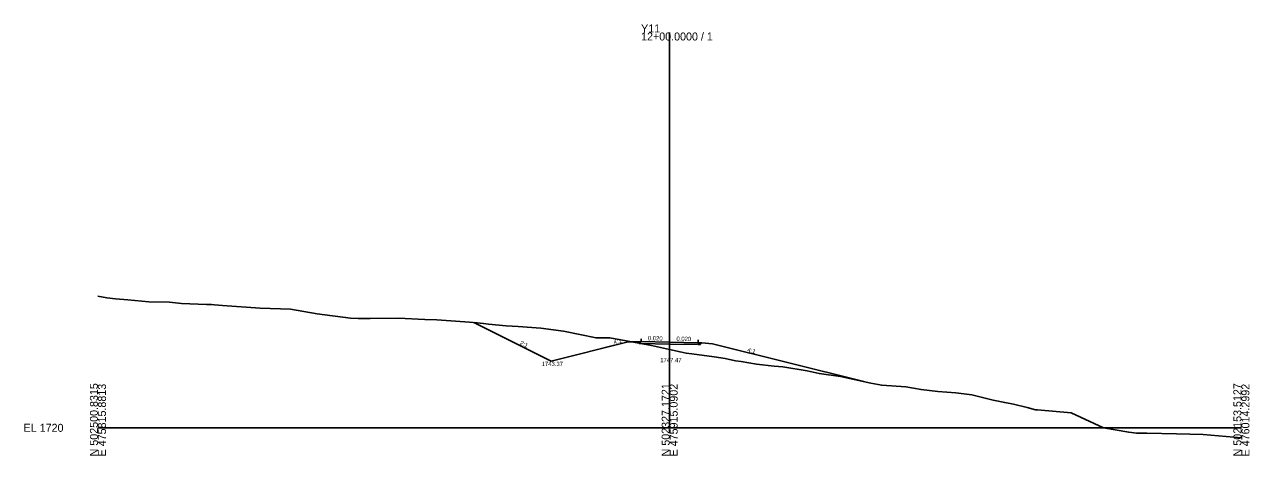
# Model space of a CAD drawing. Extents: x -76 to 353, y -10 to 8186.
# Drawn here: x -75.7 to 352.8, y 3990.3 to 4141.1 of the extents above; entities that cross this region are included whole.
import ezdxf

# ---------------------------------------------------------------- set-up
doc = ezdxf.new("R2010")
doc.units = 0
for name, color, linetype in [('Exist Cross Section Cell', 7, 'Continuous'), ('Exist XS Center Line Elevation Label', 7, 'Continuous'), ('Exist XS Ground Line', 7, 'Continuous'), ('Prop XS Ditch Slope Text', 7, 'Continuous'), ('Prop XS Ditch Standard Text', 7, 'Continuous'), ('Prop XS Dump Level', 7, 'Continuous'), ('Prop XS Earthwork Shape', 7, 'Continuous'), ('Prop XS EOT Tick Mark', 7, 'Continuous'), ('Prop XS Finish Grade', 7, 'Continuous'), ('Prop XS Finish Grade Earthwork', 7, 'Continuous'), ('Prop XS Finish Grade Pavement', 7, 'Continuous'), ('Prop XS Hydro Fill Slope Data', 7, 'Continuous'), ('Prop XS Hydro Typical Ditch Data', 7, 'Continuous'), ('Prop XS Pvmt Edge Slope', 7, 'Continuous'), ('Prop XS SE Text', 7, 'Continuous'), ('Prop XS Shoulder Borrow Shape', 7, 'Continuous'), ('Prop XS Side Slope Text', 7, 'Continuous'), ('Prop XS Subgrade Earthwork', 7, 'Continuous')]:
    doc.layers.add(name, color=color, linetype=linetype)

msp = doc.modelspace()

# ---------------------------------------------------------------- linework, layer by layer
at = {"layer": 'Exist Cross Section Cell'}
for p, q in [((150, 4000), (150, 4138.35)), ((-50, 4000), (150, 4000)), ((150, 4000), (350, 4000))]:
    msp.add_line(p, q, dxfattribs=at)
at = {"layer": 'Exist XS Ground Line'}
msp.add_lwpolyline([(-50, 4046.12), (-46.92, 4045.52), (-43.81, 4045.11), (-39.59, 4044.8), (-32.2, 4044.11), (-24.93, 4044.02), (-20.77, 4043.48), (-12.03, 4043.11), (-10.26, 4043.12), (-9.25, 4042.99), (-6.37, 4042.75), (6.73, 4041.86), (17.36, 4041.48), (26.71, 4039.85), (38.39, 4038.42), (41.08, 4038.27), (42.21, 4038.23), (45.27, 4038.22), (55.13, 4038.34), (64.39, 4037.93), (68.59, 4037.78), (79.92, 4037.02), (84.82, 4036.55), (86.63, 4036.31), (92.85, 4035.72), (97.03, 4035.45), (104.88, 4034.82), (112.88, 4033.79), (124.24, 4031.45), (126.24, 4031.46), (129.11, 4031.46), (140.49, 4029.38), (143.69, 4028.77), (150, 4027.36), (153.66, 4026.54), (155.78, 4026.11), (157.75, 4025.86), (165.54, 4024.81), (169.44, 4024.23), (173.01, 4023.49), (175.05, 4023.16), (180.34, 4022.33), (186.57, 4021.61), (189.6, 4021.29), (198.09, 4019.99), (202.33, 4018.96), (209.76, 4017.93), (220.39, 4015.63), (224.18, 4014.88), (232.65, 4014.3), (237.98, 4013.39), (243.82, 4012.72), (250.09, 4012.21), (255.68, 4011.52), (263.14, 4009.72), (267.2, 4008.82), (270.25, 4008.24), (275.09, 4007.07), (277.93, 4006.24), (278.72, 4006.26), (290.42, 4005.24), (301.76, 3999.98), (310.58, 3998.42), (313.28, 3998.15), (316.87, 3998.11), (327.36, 3997.85), (336.61, 3997.7), (347.39, 3996.74), (350, 3996.48)], dxfattribs=at)
at = {"layer": 'Prop XS Dump Level'}
for p, q in [((140, 4030.19), (150, 4029.99)), ((150, 4029.99), (160, 4029.79))]:
    msp.add_line(p, q, dxfattribs=at)
at = {"layer": 'Prop XS Earthwork Shape'}
for points in [[(112.88, 4033.79), (124.24, 4031.45), (126.24, 4031.46), (129.11, 4031.46), (136.74, 4030.06), (135, 4029.99), (108.51, 4023.37), (81.52, 4036.87), (84.82, 4036.55), (86.63, 4036.31), (92.85, 4035.72), (97.03, 4035.45), (104.88, 4034.82)], [(139.29, 4029.6), (138.74, 4030.14), (136.74, 4030.06)], [(139.29, 4029.6), (139.64, 4029.53), (139.35, 4029.54)], [(169.44, 4024.23), (173.01, 4023.49), (175.05, 4023.16), (180.34, 4022.33), (186.57, 4021.61), (189.6, 4021.29), (198.09, 4019.99), (202.33, 4018.96), (209.76, 4017.93), (217.96, 4016.15), (165, 4029.39), (161.26, 4029.69), (160.68, 4029.11), (160, 4029.13), (150, 4029.33), (140, 4029.53), (139.64, 4029.53), (140.49, 4029.38), (143.69, 4028.77), (150, 4027.36), (153.66, 4026.54), (155.78, 4026.11), (157.75, 4025.86), (165.54, 4024.81)]]:
    msp.add_lwpolyline(points, close=True, dxfattribs=at)
at = {"layer": 'Prop XS EOT Tick Mark'}
for p, q in [((140, 4030.19), (140, 4031.19)), ((160, 4029.79), (160, 4030.79))]:
    msp.add_line(p, q, dxfattribs=at)
at = {"layer": 'Prop XS Finish Grade'}
for p, q in [((140, 4030.19), (138.74, 4030.14)), ((160, 4029.79), (161.26, 4029.69))]:
    msp.add_line(p, q, dxfattribs=at)
at = {"layer": 'Prop XS Finish Grade Earthwork'}
for p, q in [((108.51, 4023.37), (81.52, 4036.87)), ((135, 4029.99), (108.51, 4023.37)), ((138.74, 4030.14), (135, 4029.99)), ((161.26, 4029.69), (165, 4029.39)), ((165, 4029.39), (217.96, 4016.15))]:
    msp.add_line(p, q, dxfattribs=at)
at = {"layer": 'Prop XS Finish Grade Pavement'}
for p, q in [((140, 4030.19), (150, 4029.99)), ((150, 4029.99), (160, 4029.79))]:
    msp.add_line(p, q, dxfattribs=at)
at = {"layer": 'Prop XS Hydro Fill Slope Data'}
msp.add_line((165, 4029.39), (217.96, 4016.15), dxfattribs=at)
at = {"layer": 'Prop XS Hydro Typical Ditch Data'}
msp.add_line((135, 4029.99), (127, 4027.99), dxfattribs=at)
at = {"layer": 'Prop XS Pvmt Edge Slope'}
for p, q in [((140, 4030.19), (139.35, 4029.54)), ((160, 4029.79), (160.68, 4029.11))]:
    msp.add_line(p, q, dxfattribs=at)
at = {"layer": 'Prop XS Shoulder Borrow Shape'}
for points in [[(139.35, 4029.54), (138.74, 4030.14), (140, 4030.19)], [(139.35, 4029.54), (138.74, 4030.14), (140, 4030.19)], [(160, 4029.79), (161.26, 4029.69), (160.68, 4029.11)], [(160, 4029.79), (161.26, 4029.69), (160.68, 4029.11)]]:
    msp.add_lwpolyline(points, close=True, dxfattribs=at)
at = {"layer": 'Prop XS Subgrade Earthwork'}
for p, q in [((139.35, 4029.54), (138.74, 4030.14)), ((140, 4029.53), (139.35, 4029.54)), ((150, 4029.33), (140, 4029.53)), ((160, 4029.13), (150, 4029.33)), ((160, 4029.13), (160.68, 4029.11)), ((160.68, 4029.11), (161.26, 4029.69))]:
    msp.add_line(p, q, dxfattribs=at)

# ---------------------------------------------------------------- texts
at = {"layer": 'Exist Cross Section Cell'}
for s, p in [('Y11', (140, 4138.35)), ('12+00.0000 / 1', (140, 4135.55)), ('EL 1720', (-76, 3998.6))]:
    msp.add_text(s, height=2.8, dxfattribs=at).set_placement(p)
for s, p in [('N 502500.8315', (-50, 3990)), ('N 502327.1721', (150, 3990)), ('N 502153.5127', (350, 3990)), ('E 475815.8813', (-47.2, 3990)), ('E 475915.0902', (152.8, 3990)), ('E 476014.2992', (352.8, 3990))]:
    msp.add_text(s, height=2.8, rotation=90, dxfattribs=at).set_placement(p)
at = {"layer": 'Exist XS Center Line Elevation Label'}
msp.add_text('1747.47', height=1.5, dxfattribs=at).set_placement((146.69, 4022.97))
at = {"layer": 'Prop XS Ditch Slope Text'}
msp.add_text('4:1', height=1.5, rotation=14.0362, dxfattribs=at).set_placement((130.55, 4029.18))
at = {"layer": 'Prop XS Ditch Standard Text'}
msp.add_text('1743.37', height=1.5, dxfattribs=at).set_placement((105.2, 4021.62))
at = {"layer": 'Prop XS Dump Level'}
for p in [(135, 4029.95), (165, 4029.35)]:
    msp.add_text('Case1', height=0.04, dxfattribs=at).set_placement(p)
at = {"layer": 'Prop XS SE Text'}
for p in [(142.35, 4030.65), (152.35, 4030.45)]:
    msp.add_text('0.020', height=1.5, rotation=358.8542, dxfattribs=at).set_placement(p)
at = {"layer": 'Prop XS Side Slope Text'}
for s, rotation, p in [('2:1', 333.4349, (97.43, 4029.24)), ('4:1', 345.9638, (177.07, 4026.63))]:
    msp.add_text(s, height=1.5, rotation=rotation, dxfattribs=at).set_placement(p)

doc.saveas('drawing.dxf')
